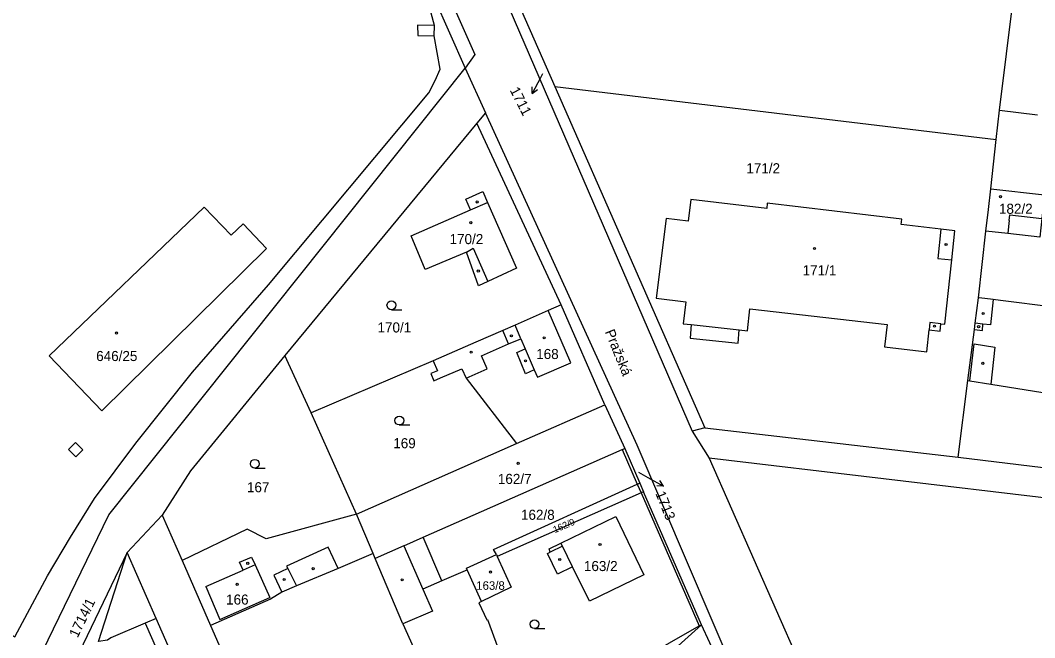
# Model space of a CAD drawing. Extents: x -724107 to -720612, y -1045267 to -1038441.
# Drawn here: x -722991.4 to -722820.2, y -1042319 to -1042214.9 of the extents above; entities that cross this region are included whole.
import ezdxf

# ---------------------------------------------------------------- set-up
doc = ezdxf.new("R2010")
doc.units = 0
for name, color, linetype in [('Hranice parcel', 7, 'Continuous'), ('Parcelní čísla', 7, 'Continuous'), ('Pop  PČ popisy', 7, 'Continuous'), ('Vnitřní kresba', 7, 'Continuous'), ('Značky budov', 7, 'Continuous'), ('Značky kultur', 7, 'Continuous')]:
    doc.layers.add(name, color=color, linetype=linetype)

msp = doc.modelspace()

# ---------------------------------------------------------------- linework, layer by layer
at = {"layer": 'Hranice parcel'}
for p, q in [((-722961.18, -1042120.94), (-722916.3, -1042223.03)), ((-722924.33, -1042177.14), (-722877.98, -1042284.23)), ((-722826.13, -1042230.09), (-722823.54, -1042209.11)), ((-722916.3, -1042223.03), (-722912.87, -1042230.53)), ((-722912.87, -1042230.53), (-722914.31, -1042232.27)), ((-722826.13, -1042230.09), (-722819.69, -1042230.9)), ((-722914.31, -1042232.27), (-722946.71, -1042271.48)), ((-722900.12, -1042262.93), (-722914.31, -1042232.27)), ((-722829.69, -1042261.74), (-722828.42, -1042250.49)), ((-722892.71, -1042279.76), (-722900.12, -1042262.93)), ((-722942.27, -1042281.11), (-722946.71, -1042271.48)), ((-722921.71, -1042272.35), (-722942.27, -1042281.11)), ((-722833.08, -1042288.59), (-722831.45, -1042275.7)), ((-722934.62, -1042298.2), (-722942.27, -1042281.11)), ((-722907.62, -1042286.32), (-722892.71, -1042279.76)), ((-722892.71, -1042279.76), (-722889.38, -1042287.14)), ((-722875.83, -1042283.68), (-722877.98, -1042284.23)), ((-722877.98, -1042284.23), (-722875.11, -1042288.78)), ((-722875.83, -1042283.68), (-722833.08, -1042288.59)), ((-722934.62, -1042298.2), (-722907.62, -1042286.32)), ((-722889.38, -1042287.14), (-722886.84, -1042292.96)), ((-722875.11, -1042288.78), (-722824.01, -1042404.46)), ((-722733.27, -1042305.52), (-722875.11, -1042288.78)), ((-722886.84, -1042292.96), (-722886.19, -1042294.45)), ((-722876.41, -1042316.85), (-722886.19, -1042294.45)), ((-722967.41, -1042298.39), (-722973.34, -1042304.66)), ((-722967.41, -1042298.39), (-722964.07, -1042306.01)), ((-722931.85, -1042304.87), (-722934.62, -1042298.2)), ((-722973.34, -1042304.66), (-722987.16, -1042333.34)), ((-722978.17, -1042319.68), (-722973.34, -1042304.66)), ((-722911.02, -1042305.02), (-722910.87, -1042305.35)), ((-722964.07, -1042306.01), (-722959.26, -1042316.99)), ((-722913.56, -1042312.92), (-722915.94, -1042307.59)), ((-722926.79, -1042316.73), (-722921.11, -1042329.42)), ((-722876.41, -1042316.85), (-722905.85, -1042343.37)), ((-722870.21, -1042330.38), (-722876.41, -1042316.85))]:
    msp.add_line(p, q, dxfattribs=at)
for points in [[(-723067.58, -1042304.26), (-723050.74, -1042288.65), (-723047.02, -1042289.7), (-723039.4, -1042292.02), (-722992.3, -1042318.88), (-722986.79, -1042308.63), (-722982.91, -1042302.08), (-722978.85, -1042295.55), (-722971.9, -1042286.23), (-722962.29, -1042274.3), (-722949.46, -1042259.57), (-722922.43, -1042227.19), (-722921.35, -1042225.1), (-722920.54, -1042223.19), (-722921.53, -1042217.58), (-722921.47, -1042215.83), (-722922.44, -1042212.29), (-722961.05, -1042124.71), (-722962.26, -1042121.96)], [(-722913.24, -1042198.62), (-722901.16, -1042226.1), (-722875.83, -1042283.68)], [(-723030.78, -1042459.85), (-723021.53, -1042422.08), (-722994.15, -1042334.83), (-722976.41, -1042298.3), (-722916.3, -1042223.03)], [(-722865.95, -1042336.37), (-722887.25, -1042286.6), (-722912.87, -1042230.53)], [(-722827.62, -1042243.37), (-722826.69, -1042235.05), (-722826.13, -1042230.09)], [(-722828.42, -1042250.49), (-722828.01, -1042246.83), (-722827.62, -1042243.37)], [(-722827.62, -1042243.37), (-722818.52, -1042244.4), (-722818.91, -1042247.87)], [(-722912.48, -1042258.98), (-722914.02, -1042259.69), (-722916.05, -1042254.03), (-722923.06, -1042256.94), (-722925.4, -1042251.31), (-722915.41, -1042246.91), (-722916.2, -1042245.13), (-722913.33, -1042243.83), (-722912.53, -1042245.64), (-722907.64, -1042256.75), (-722912.48, -1042258.98)], [(-722884.04, -1042261.77), (-722879.08, -1042262.42), (-722879.51, -1042266.1), (-722878.16, -1042266.25), (-722878.35, -1042268.55), (-722870.24, -1042269.41), (-722870.07, -1042267.14), (-722868.66, -1042267.29), (-722868.24, -1042263.6), (-722845.11, -1042266.26), (-722845.54, -1042270), (-722838.37, -1042270.83), (-722838.01, -1042267.15), (-722836.17, -1042267.35), (-722836.05, -1042266.1), (-722835.33, -1042266.17), (-722834.18, -1042255.35), (-722833.66, -1042250.43), (-722836.03, -1042250.18), (-722842.7, -1042249.4), (-722842.59, -1042248.49), (-722865.31, -1042245.8), (-722865.42, -1042246.67), (-722878.19, -1042245.16), (-722878.68, -1042248.83), (-722882.39, -1042248.38), (-722884.04, -1042261.77)], [(-722977.59, -1042280.77), (-722986.48, -1042271.5), (-722960.36, -1042246.45), (-722955.77, -1042251.17), (-722953.78, -1042249.24), (-722949.83, -1042253.41), (-722977.59, -1042280.77)], [(-722818.91, -1042247.87), (-722818.97, -1042248.36), (-722819.32, -1042251.52), (-722824.75, -1042250.91), (-722828.42, -1042250.49)], [(-722831.45, -1042275.7), (-722830.34, -1042267.06), (-722830.21, -1042266.03), (-722829.69, -1042261.74)], [(-722805.53, -1042264.69), (-722811.72, -1042263.93), (-722815.89, -1042263.43), (-722817.01, -1042263.29), (-722825.95, -1042262.2), (-722827.21, -1042262.04), (-722829.54, -1042261.76), (-722829.69, -1042261.74)], [(-722900.12, -1042262.93), (-722902.27, -1042263.89), (-722907.87, -1042266.33), (-722909.95, -1042267.23), (-722914.47, -1042269.2), (-722921.71, -1042272.35)], [(-722946.71, -1042271.48), (-722962.64, -1042290.91), (-722967.41, -1042298.39)], [(-722921.71, -1042272.35), (-722920.99, -1042274.04), (-722922.11, -1042274.52), (-722921.6, -1042275.71), (-722920.48, -1042275.24), (-722916.84, -1042273.69), (-722916.13, -1042275.3), (-722907.62, -1042286.32)], [(-722831.45, -1042275.7), (-722831.11, -1042275.76), (-722827.62, -1042276.32), (-722807.24, -1042279.58)], [(-722833.08, -1042288.59), (-722808.59, -1042291.58), (-722807.24, -1042279.58)], [(-722920.21, -1042309.46), (-722923.4, -1042302.12), (-722914.92, -1042298.39), (-722913.55, -1042297.78), (-722889.79, -1042287.32), (-722889.38, -1042287.14)], [(-722911.02, -1042305.02), (-722911.49, -1042304.18), (-722887.25, -1042293.15), (-722886.84, -1042292.96)], [(-722886.19, -1042294.45), (-722886.6, -1042294.63), (-722910.87, -1042305.35)], [(-722934.62, -1042298.2), (-722949.89, -1042302.39), (-722953.07, -1042300.73), (-722964.07, -1042306.01)], [(-722902.41, -1042304.85), (-722901.98, -1042304.64), (-722902.15, -1042304.04), (-722900.17, -1042303.08), (-722890.9, -1042298.6), (-722886.15, -1042308.42), (-722895.32, -1042312.89), (-722898.2, -1042307.07), (-722900.7, -1042308.31), (-722902.41, -1042304.85)], [(-722931.85, -1042304.87), (-722937.72, -1042307.35), (-722944.74, -1042310.32), (-722947.23, -1042311.37), (-722949.15, -1042312.52), (-722959.26, -1042316.99)], [(-722926.79, -1042316.73), (-722931.51, -1042305.69), (-722931.85, -1042304.87)], [(-722915.94, -1042307.59), (-722916.07, -1042307.33), (-722911.02, -1042305.02)], [(-722910.87, -1042305.35), (-722908.52, -1042310.55), (-722913.56, -1042312.92)], [(-722915.94, -1042307.59), (-722916.32, -1042307.76), (-722920.21, -1042309.46)], [(-722920.21, -1042309.46), (-722923.45, -1042310.87), (-722921.83, -1042314.55), (-722926.79, -1042316.73)], [(-722913.56, -1042312.92), (-722914, -1042313.18), (-722912.66, -1042316.01), (-722912.52, -1042315.95), (-722910.72, -1042320.84), (-722906.48, -1042330.75), (-722918.2, -1042335.92)], [(-722962.35, -1042329.63), (-722968.46, -1042315.81), (-722970.3, -1042316.58), (-722976.1, -1042319.07), (-722976.64, -1042319.44), (-722978.17, -1042319.68)], [(-722959.26, -1042316.99), (-722948.46, -1042341.61), (-722934.71, -1042372.64)], [(-722916.48, -1042339.75), (-722876.8, -1042317.07), (-722876.41, -1042316.85)]]:
    msp.add_lwpolyline(points, dxfattribs=at)
at = {"layer": 'Pop  PČ popisy'}
for p, q in [((-722903.6, -1042224.63), (-722905.01, -1042227.28)), ((-722903.26, -1042223.99), (-722903.6, -1042224.63)), ((-722905.01, -1042227.28), (-722904.98, -1042226.16)), ((-722905.01, -1042227.28), (-722904.1, -1042226.63)), ((-722887.06, -1042291.13), (-722885.45, -1042292.02)), ((-722885.45, -1042292.02), (-722882.83, -1042293.47)), ((-722882.83, -1042293.47), (-722883.46, -1042292.55)), ((-722882.83, -1042293.47), (-722883.94, -1042293.43))]:
    msp.add_line(p, q, dxfattribs=at)
at = {"layer": 'Vnitřní kresba'}
for p, q in [((-722989.39, -1042050.97), (-722914.69, -1042220.69)), ((-722921.47, -1042215.83), (-722924.34, -1042215.78)), ((-722924.34, -1042215.78), (-722924.29, -1042217.52)), ((-722924.29, -1042217.52), (-722921.53, -1042217.58)), ((-722914.69, -1042220.69), (-722916.3, -1042223.03)), ((-722901.16, -1042226.1), (-722826.69, -1042235.05)), ((-722915.41, -1042246.91), (-722912.53, -1042245.64)), ((-722824.48, -1042248.71), (-722824.6, -1042249.7)), ((-722836.03, -1042250.18), (-722836.55, -1042255.1)), ((-722824.6, -1042249.7), (-722824.75, -1042250.91)), ((-722916.05, -1042254.03), (-722914.93, -1042253.36)), ((-722914.93, -1042253.36), (-722912.48, -1042258.98)), ((-722836.55, -1042255.1), (-722834.18, -1042255.35)), ((-722827.21, -1042262.04), (-722827.67, -1042266.3)), ((-722898.49, -1042272.68), (-722902.27, -1042263.89)), ((-722909, -1042269.49), (-722909.95, -1042267.23)), ((-722906.88, -1042268.63), (-722907.87, -1042266.33)), ((-722878.16, -1042266.25), (-722870.07, -1042267.14)), ((-722837.89, -1042265.92), (-722838.01, -1042267.15)), ((-722836.05, -1042266.1), (-722837.89, -1042265.92)), ((-722830.34, -1042267.06), (-722829, -1042267.23)), ((-722828.95, -1042266.16), (-722830.21, -1042266.03)), ((-722829, -1042267.23), (-722828.95, -1042266.16)), ((-722827.67, -1042266.3), (-722828.95, -1042266.16)), ((-722909, -1042269.49), (-722906.88, -1042268.63)), ((-722906.88, -1042268.63), (-722906.15, -1042270.34)), ((-722913.54, -1042271.54), (-722909, -1042269.49)), ((-722907.6, -1042270.96), (-722906.15, -1042270.34)), ((-722906.09, -1042274.53), (-722907.6, -1042270.96)), ((-722906.15, -1042270.34), (-722904.64, -1042273.86)), ((-722831.11, -1042275.76), (-722830.39, -1042269.49)), ((-722830.39, -1042269.49), (-722826.89, -1042270.03)), ((-722826.89, -1042270.03), (-722827.62, -1042276.32)), ((-722912.57, -1042273.73), (-722913.54, -1042271.54)), ((-722904.1, -1042275.12), (-722898.49, -1042272.68)), ((-722916.13, -1042275.3), (-722912.57, -1042273.73)), ((-722904.64, -1042273.86), (-722906.09, -1042274.53)), ((-722904.64, -1042273.86), (-722904.1, -1042275.12)), ((-722983.25, -1042287.29), (-722982.07, -1042286.13)), ((-722982.07, -1042286.13), (-722980.82, -1042287.35)), ((-722982.02, -1042288.55), (-722983.25, -1042287.29)), ((-722980.82, -1042287.35), (-722982.02, -1042288.55)), ((-722889.79, -1042287.32), (-722887.25, -1042293.15)), ((-722887.25, -1042293.15), (-722886.6, -1042294.63)), ((-722886.6, -1042294.63), (-722876.8, -1042317.07)), ((-722926.67, -1042303.56), (-722923.4, -1042302.12)), ((-722899.9, -1042303.62), (-722900.17, -1042303.08)), ((-722968.46, -1042315.81), (-722973.34, -1042304.66)), ((-722939.4, -1042303.77), (-722946.43, -1042306.99)), ((-722937.72, -1042307.35), (-722939.4, -1042303.77)), ((-722926.67, -1042303.56), (-722931.51, -1042305.69)), ((-722926.67, -1042303.56), (-722923.45, -1042310.87)), ((-722899.9, -1042303.62), (-722901.98, -1042304.64)), ((-722898.2, -1042307.07), (-722899.9, -1042303.62)), ((-722954.37, -1042306.31), (-722952.37, -1042305.44)), ((-722953.78, -1042307.65), (-722954.37, -1042306.31)), ((-722951.74, -1042306.76), (-722953.78, -1042307.65)), ((-722952.37, -1042305.44), (-722951.74, -1042306.76)), ((-722951.74, -1042306.76), (-722949.27, -1042312.25)), ((-722960.08, -1042310.41), (-722953.78, -1042307.65)), ((-722946.24, -1042307.36), (-722948.6, -1042308.48)), ((-722948.6, -1042308.48), (-722947.23, -1042311.37)), ((-722946.43, -1042306.99), (-722946.24, -1042307.36)), ((-722946.24, -1042307.36), (-722944.74, -1042310.32)), ((-722960.08, -1042310.41), (-722957.67, -1042315.96)), ((-722957.67, -1042315.96), (-722949.27, -1042312.25)), ((-722970.3, -1042316.58), (-722968.38, -1042320.91))]:
    msp.add_line(p, q, dxfattribs=at)
msp.add_lwpolyline([(-722824.48, -1042248.71), (-722824.36, -1042247.76), (-722818.97, -1042248.36)], dxfattribs=at)
at = {"layer": 'Značky budov'}
for centre in [(-722825.95, -1042244.68), (-722914.28, -1042245.58), (-722915.34, -1042249.07), (-722857.34, -1042253.43), (-722835.15, -1042252.76), (-722914.08, -1042257.22), (-722828.89, -1042264.39), (-722975.13, -1042267.67), (-722837.11, -1042266.51), (-722829.65, -1042266.6), (-722908.5, -1042268.13), (-722902.97, -1042268.5), (-722915.27, -1042270.91), (-722906.12, -1042272.35), (-722828.93, -1042272.78), (-722907.35, -1042289.65), (-722893.54, -1042303.34), (-722952.99, -1042306.5), (-722900.34, -1042305.85), (-722941.95, -1042307.4), (-722912.02, -1042307.97), (-722954.77, -1042310.04), (-722946.85, -1042309.24), (-722926.94, -1042309.3)]:
    msp.add_circle(centre, 0.175, dxfattribs=at)
at = {"layer": 'Značky kultur'}
for p, q in [((-722928.74, -1042263.74), (-722926.99, -1042263.74)), ((-722927.41, -1042283.18), (-722925.66, -1042283.18)), ((-722951.8, -1042290.47), (-722950.05, -1042290.47)), ((-722904.6, -1042317.52), (-722902.85, -1042317.52))]:
    msp.add_line(p, q, dxfattribs=at)
for centre in [(-722928.74, -1042262.99), (-722927.41, -1042282.43), (-722951.8, -1042289.72), (-722904.6, -1042316.77)]:
    msp.add_circle(centre, 0.75, dxfattribs=at)

# ---------------------------------------------------------------- texts
at = {"layer": 'Parcelní čísla'}
for s, height, rotation, p in [('1711', 1.7, 297, (-722908.81, -1042226.71)), ('1713', 1.7, 292, (-722884.22, -1042294.72)), ('162/9', 1.139, 23, (-722901.17, -1042301.42)), ('1714/1', 1.7, 64, (-722981.7, -1042319.17))]:
    msp.add_text(s, height=height, rotation=rotation, dxfattribs=at).set_placement(p)
for s, height, p in [('171/2', 1.7, (-722868.85, -1042240.74)), ('182/2', 1.7, (-722826.22, -1042247.57)), ('170/2', 1.7, (-722918.93, -1042252.68)), ('171/1', 1.7, (-722859.35, -1042257.94)), ('170/1', 1.7, (-722931.09, -1042267.58)), ('646/25', 1.7, (-722978.56, -1042272.4)), ('168', 1.7, (-722904.31, -1042272.06)), ('169', 1.7, (-722928.43, -1042287.1)), ('162/7', 1.7, (-722910.78, -1042293.12)), ('167', 1.7, (-722953.12, -1042294.52)), ('162/8', 1.7, (-722906.88, -1042299.17)), ('163/2', 1.7, (-722896.26, -1042307.81)), ('163/8', 1.439, (-722914.43, -1042310.97)), ('166', 1.7, (-722956.64, -1042313.46))]:
    msp.add_text(s, height=height, dxfattribs=at).set_placement(p)
at = {"layer": 'Pop  PČ popisy'}
msp.add_text('Pražská', height=1.7, rotation=292, dxfattribs=at).set_placement((-722892.75, -1042267.46))

doc.saveas('drawing.dxf')
